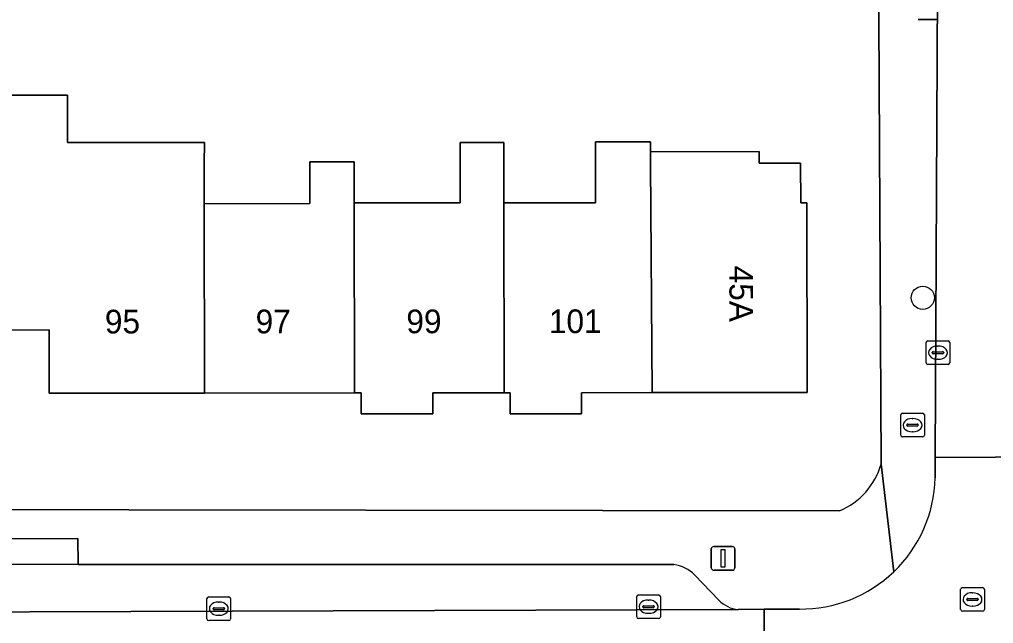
# Model space of a CAD drawing. Extents: x 160732 to 162107, y 387428 to 388479.
# Drawn here: x 161117.3 to 161158.48, y 388134.52 to 388160.04 of the extents above; entities that cross this region are included whole.
import ezdxf

# ---------------------------------------------------------------- set-up
doc = ezdxf.new("R2010")
doc.units = 0
for name, color, linetype in [('IMGEO_Boom', 7, 'Continuous'), ('IMGEO_Brandkraan', 7, 'Continuous'), ('IMGEO_Erf', 7, 'Continuous'), ('IMGEO_Kolk', 7, 'Continuous'), ('IMGEO_Lichtmast', 7, 'Continuous'), ('IMGEO_Pand', 7, 'Continuous'), ('IMGEO_Pand_nummerreeks', 7, 'Continuous'), ('IMGEO_Parkeervlak_open', 7, 'Continuous'), ('IMGEO_Rijbaan_lokaal_open', 7, 'Continuous'), ('IMGEO_Rioolput', 7, 'Continuous'), ('IMGEO_Voetpad_open', 7, 'Continuous')]:
    doc.layers.add(name, color=color, linetype=linetype)

msp = doc.modelspace()

# ---------------------------------------------------------------- linework, layer by layer
at = {"layer": 'IMGEO_Boom'}
msp.add_circle((161155.494, 388148.283), 0.489, dxfattribs=at)
at = {"layer": 'IMGEO_Brandkraan'}
for p, q in [((161154.56, 388142.478), (161154.56, 388143.33)), ((161154.635, 388143.404), (161155.487, 388143.404)), ((161155.561, 388143.33), (161155.561, 388142.478)), ((161154.819, 388142.898), (161154.819, 388142.91)), ((161155.257, 388142.861), (161154.859, 388142.861)), ((161154.862, 388142.947), (161155.26, 388142.947)), ((161155.048, 388143.184), (161155.073, 388143.184)), ((161155.303, 388142.91), (161155.303, 388142.898)), ((161155.071, 388142.624), (161155.046, 388142.624)), ((161155.487, 388142.404), (161154.635, 388142.404))]:
    msp.add_line(p, q, dxfattribs=at)
for points in [[(161154.56, 388142.478), (161154.56, 388143.33)], [(161154.635, 388143.404), (161155.487, 388143.404)], [(161155.561, 388143.33), (161155.561, 388142.478)], [(161155.487, 388142.404), (161154.635, 388142.404)]]:
    msp.add_lwpolyline(points, dxfattribs=at)
for centre, radius, start, end in [((161154.637, 388143.328), 0.0765, 91.552, 178.448), ((161154.637, 388143.328), 0.0765, 91.552, 178.448), ((161155.485, 388143.328), 0.0765, 1.552, 88.448), ((161155.485, 388143.328), 0.0765, 1.552, 88.448), ((161154.859, 388142.907), 0.0403, 85.8775, 175.7526), ((161154.856, 388142.897), 0.0366, 178.938, 274.7102), ((161155.26, 388142.904), 0.043, 264.8664, 352.4533), ((161155.264, 388142.909), 0.0386, 1.7309, 96.639), ((161154.637, 388142.48), 0.0765, 181.552, 268.448), ((161154.637, 388142.48), 0.0765, 181.552, 268.448), ((161155.485, 388142.48), 0.0765, 271.552, 358.448), ((161155.485, 388142.48), 0.0765, 271.552, 358.448)]:
    msp.add_arc(centre, radius, start, end, dxfattribs=at)
for centre, major_axis, ratio, start_param, end_param in [((161155.047, 388142.904), (-0.387, 0.002), 0.722429, 4.712389, 7.853982), ((161155.072, 388142.904), (-0.39, 0.002), 0.717154, 1.570796, 4.712389)]:
    msp.add_ellipse(centre, major_axis=major_axis, ratio=ratio, start_param=start_param, end_param=end_param, dxfattribs=at)
at = {"layer": 'IMGEO_Erf'}
for points in [[(161153.729, 388141.259), (161153.611, 388165.456)], [(161114.927, 388156.851), (161119.327, 388156.851), (161119.327, 388154.851), (161125.122, 388154.851), (161125.111, 388153.956), (161125.113, 388152.259), (161129.583, 388152.262), (161129.581, 388154.025), (161131.454, 388154.026), (161131.455, 388152.296), (161135.932, 388152.3), (161135.93, 388153.961), (161135.929, 388154.839), (161137.783, 388154.84), (161137.784, 388153.963), (161137.785, 388152.297), (161141.655, 388152.3), (161141.653, 388154.868), (161143.981, 388154.869), (161143.984, 388154.444), (161148.568, 388154.468), (161148.571, 388153.968), (161150.329, 388153.969), (161150.331, 388152.298), (161150.593, 388152.299), (161150.6, 388144.279), (161144.045, 388144.274), (161141.066, 388144.272), (161141.066, 388143.374), (161138.043, 388143.374), (161138.043, 388144.269), (161137.79, 388144.269), (161134.772, 388144.267), (161134.772, 388143.374), (161131.749, 388143.374), (161131.749, 388144.264), (161131.46, 388144.264), (161125.122, 388144.259), (161118.554, 388144.254), (161118.552, 388146.923), (161114.927, 388146.921)], [(161091.402, 388139.194), (161098.635, 388139.224), (161111.891, 388139.34), (161151.971, 388139.278)]]:
    msp.add_lwpolyline(points, dxfattribs=at)
msp.add_arc((161150.813, 388142.076), 3.028, 292.4783, 344.3481, dxfattribs=at)
at = {"layer": 'IMGEO_Kolk'}
for p, q in [((161155.633, 388145.537), (161155.633, 388146.389)), ((161155.708, 388146.463), (161156.56, 388146.463)), ((161156.121, 388146.243), (161156.146, 388146.243)), ((161156.634, 388146.389), (161156.634, 388145.537)), ((161155.892, 388145.957), (161155.892, 388145.969)), ((161156.33, 388145.92), (161155.932, 388145.92)), ((161155.935, 388146.006), (161156.333, 388146.006)), ((161156.376, 388145.969), (161156.376, 388145.957)), ((161156.56, 388145.463), (161155.708, 388145.463)), ((161156.144, 388145.683), (161156.119, 388145.683)), ((161125.228, 388134.719), (161125.228, 388135.571)), ((161125.303, 388135.645), (161126.155, 388135.645)), ((161125.716, 388135.425), (161125.741, 388135.425)), ((161126.229, 388135.571), (161126.229, 388134.719)), ((161143.396, 388134.803), (161143.396, 388135.655)), ((161143.471, 388135.729), (161144.323, 388135.729)), ((161143.884, 388135.509), (161143.909, 388135.509)), ((161144.397, 388135.655), (161144.397, 388134.803)), ((161125.487, 388135.139), (161125.487, 388135.151)), ((161125.925, 388135.102), (161125.527, 388135.102)), ((161125.53, 388135.188), (161125.928, 388135.188)), ((161125.971, 388135.151), (161125.971, 388135.139)), ((161143.655, 388135.223), (161143.655, 388135.235)), ((161144.093, 388135.186), (161143.695, 388135.186)), ((161143.698, 388135.272), (161144.096, 388135.272)), ((161144.139, 388135.235), (161144.139, 388135.223)), ((161126.155, 388134.645), (161125.303, 388134.645)), ((161125.739, 388134.865), (161125.714, 388134.865)), ((161144.323, 388134.729), (161143.471, 388134.729)), ((161143.907, 388134.949), (161143.882, 388134.949))]:
    msp.add_line(p, q, dxfattribs=at)
for points in [[(161155.633, 388145.537), (161155.633, 388146.389)], [(161155.708, 388146.463), (161156.56, 388146.463)], [(161156.634, 388146.389), (161156.634, 388145.537)], [(161156.56, 388145.463), (161155.708, 388145.463)], [(161125.228, 388134.719), (161125.228, 388135.571)], [(161125.303, 388135.645), (161126.155, 388135.645)], [(161126.229, 388135.571), (161126.229, 388134.719)], [(161143.396, 388134.803), (161143.396, 388135.655)], [(161143.471, 388135.729), (161144.323, 388135.729)], [(161144.397, 388135.655), (161144.397, 388134.803)], [(161126.155, 388134.645), (161125.303, 388134.645)], [(161144.323, 388134.729), (161143.471, 388134.729)]]:
    msp.add_lwpolyline(points, dxfattribs=at)
for centre, radius, start, end in [((161155.71, 388146.387), 0.0765, 91.552, 178.448), ((161155.71, 388146.387), 0.0765, 91.552, 178.448), ((161156.558, 388146.387), 0.0765, 1.552, 88.448), ((161156.558, 388146.387), 0.0765, 1.552, 88.448), ((161155.932, 388145.966), 0.0403, 85.8775, 175.7526), ((161155.929, 388145.956), 0.0366, 178.938, 274.7102), ((161156.333, 388145.963), 0.043, 264.8664, 352.4533), ((161156.337, 388145.968), 0.0386, 1.7309, 96.639), ((161155.71, 388145.539), 0.0765, 181.552, 268.448), ((161155.71, 388145.539), 0.0765, 181.552, 268.448), ((161156.558, 388145.539), 0.0765, 271.552, 358.448), ((161156.558, 388145.539), 0.0765, 271.552, 358.448), ((161125.305, 388135.569), 0.0765, 91.552, 178.448), ((161125.305, 388135.569), 0.0765, 91.552, 178.448), ((161126.153, 388135.569), 0.0765, 1.552, 88.448), ((161126.153, 388135.569), 0.0765, 1.552, 88.448), ((161143.473, 388135.653), 0.0765, 91.552, 178.448), ((161143.473, 388135.653), 0.0765, 91.552, 178.448), ((161144.321, 388135.653), 0.0765, 1.552, 88.448), ((161144.321, 388135.653), 0.0765, 1.552, 88.448), ((161125.527, 388135.148), 0.0403, 85.8775, 175.7526), ((161125.524, 388135.138), 0.0366, 178.938, 274.7102), ((161125.928, 388135.145), 0.043, 264.8664, 352.4533), ((161125.932, 388135.15), 0.0386, 1.7309, 96.639), ((161143.695, 388135.232), 0.0403, 85.8775, 175.7526), ((161143.692, 388135.222), 0.0366, 178.938, 274.7102), ((161144.096, 388135.229), 0.043, 264.8664, 352.4533), ((161144.1, 388135.234), 0.0386, 1.7309, 96.639), ((161125.305, 388134.721), 0.0765, 181.552, 268.448), ((161125.305, 388134.721), 0.0765, 181.552, 268.448), ((161126.153, 388134.721), 0.0765, 271.552, 358.448), ((161126.153, 388134.721), 0.0765, 271.552, 358.448), ((161143.473, 388134.805), 0.0765, 181.552, 268.448), ((161143.473, 388134.805), 0.0765, 181.552, 268.448), ((161144.321, 388134.805), 0.0765, 271.552, 358.448), ((161144.321, 388134.805), 0.0765, 271.552, 358.448)]:
    msp.add_arc(centre, radius, start, end, dxfattribs=at)
for centre, major_axis, ratio, start_param, end_param in [((161156.12, 388145.963), (-0.387, 0.002), 0.722429, 4.712389, 7.853982), ((161156.145, 388145.963), (-0.39, 0.002), 0.717154, 1.570796, 4.712389), ((161125.715, 388135.145), (-0.387, 0.002), 0.722429, 4.712389, 7.853982), ((161125.74, 388135.145), (-0.39, 0.002), 0.717154, 1.570796, 4.712389), ((161143.883, 388135.229), (-0.387, 0.002), 0.722429, 4.712389, 7.853982), ((161143.908, 388135.229), (-0.39, 0.002), 0.717154, 1.570796, 4.712389)]:
    msp.add_ellipse(centre, major_axis=major_axis, ratio=ratio, start_param=start_param, end_param=end_param, dxfattribs=at)
at = {"layer": 'IMGEO_Lichtmast'}
for p, q in [((161156.082, 388160.042), (161155.292, 388160.042)), ((161155.292, 388160.042), (161156.082, 388160.042)), ((161146.552, 388136.871), (161146.552, 388137.671)), ((161146.552, 388137.671), (161146.552, 388136.871)), ((161146.652, 388137.771), (161147.442, 388137.771)), ((161147.442, 388137.771), (161146.652, 388137.771)), ((161147.542, 388137.671), (161147.542, 388136.871)), ((161147.542, 388136.871), (161147.542, 388137.671)), ((161147.442, 388136.771), (161146.652, 388136.771)), ((161146.652, 388136.771), (161147.442, 388136.771))]:
    msp.add_line(p, q, dxfattribs=at)
msp.add_lwpolyline([(161146.972, 388137.646), (161147.122, 388137.646), (161147.122, 388136.896), (161146.972, 388136.896), (161146.972, 388137.646)], dxfattribs=at)
for centre, start, end in [((161146.652, 388137.671), 90, 180), ((161146.652, 388137.671), 90, 180), ((161147.442, 388137.671), 0, 90), ((161147.442, 388137.671), 360, 90), ((161146.652, 388136.871), 180, 270), ((161146.652, 388136.871), 180, 270), ((161147.442, 388136.871), 270, 0), ((161147.442, 388136.871), 270, 0)]:
    msp.add_arc(centre, 0.1, start, end, dxfattribs=at)
at = {"layer": 'IMGEO_Pand'}
for points in [[(161125.122, 388154.851), (161119.327, 388154.851), (161119.327, 388156.851), (161114.927, 388156.851), (161114.922, 388154.204), (161114.927, 388146.921), (161118.552, 388146.923), (161118.554, 388144.254), (161125.122, 388144.259), (161125.113, 388152.259), (161125.111, 388153.956)], [(161137.785, 388152.297), (161137.784, 388153.963), (161137.783, 388154.84), (161135.929, 388154.839), (161135.93, 388153.961), (161135.932, 388152.3), (161131.455, 388152.296), (161131.46, 388144.264), (161131.749, 388144.264), (161131.749, 388143.374), (161134.772, 388143.374), (161134.772, 388144.267), (161137.79, 388144.269)], [(161143.987, 388153.944), (161143.984, 388154.444), (161143.981, 388154.869), (161141.653, 388154.868), (161141.655, 388152.3), (161137.785, 388152.297), (161137.79, 388144.269), (161138.043, 388144.269), (161138.043, 388143.374), (161141.066, 388143.374), (161141.066, 388144.272), (161144.045, 388144.274)], [(161144.045, 388144.274), (161150.6, 388144.279), (161150.593, 388152.299), (161150.331, 388152.298), (161150.329, 388153.969), (161148.571, 388153.968), (161148.568, 388154.468), (161143.984, 388154.444), (161143.987, 388153.944)], [(161125.122, 388144.259), (161131.46, 388144.264), (161131.455, 388152.296), (161131.454, 388154.026), (161129.581, 388154.025), (161129.583, 388152.262), (161125.113, 388152.259)]]:
    msp.add_lwpolyline(points, close=True, dxfattribs=at)
at = {"layer": 'IMGEO_Parkeervlak_open'}
for points in [[(161119.782, 388137.014), (161110.754, 388137.021)], [(161144.962, 388137.01), (161119.782, 388137.014)], [(161146.875, 388135.509), (161145.848, 388136.568)], [(161087.767, 388134.917), (161147.688, 388135.104)]]:
    msp.add_lwpolyline(points, dxfattribs=at)
for centre, radius, start, end in [((161144.762, 388135.501), 1.523, 44.5117, 82.4617), ((161147.83, 388136.407), 1.311, 223.2528, 263.7864)]:
    msp.add_arc(centre, radius, start, end, dxfattribs=at)
at = {"layer": 'IMGEO_Rijbaan_lokaal_open'}
for points in [[(161160.946, 388193.594), (161160.967, 388195.059), (161160.943, 388223.645), (161155.942, 388223.612), (161156.12, 388166.254), (161156.114, 388161.291), (161156.023, 388141.534), (161161.118, 388141.556), (161160.945, 388175.907)], [(161161.118, 388141.556), (161156.023, 388141.534), (161156.019, 388140.67)], [(161147.688, 388135.104), (161087.767, 388134.917)], [(161148.781, 388135.121), (161147.688, 388135.104)], [(161150.274, 388135.131), (161148.781, 388135.121), (161148.814, 388130.087), (161149.577, 388130.075)], [(161148.814, 388130.087), (161148.781, 388135.121)]]:
    msp.add_lwpolyline(points, dxfattribs=at)
for centre, radius, start, end in [((161150.337, 388140.812), 5.684, 313.7184, 358.5659), ((161150.343, 388140.806), 5.676, 269.3076, 313.7148)]:
    msp.add_arc(centre, radius, start, end, dxfattribs=at)
at = {"layer": 'IMGEO_Rioolput'}
for p, q in [((161157.094, 388135.112), (161157.094, 388135.964)), ((161157.169, 388136.038), (161158.021, 388136.038)), ((161157.582, 388135.818), (161157.607, 388135.818)), ((161158.095, 388135.964), (161158.095, 388135.112)), ((161157.353, 388135.532), (161157.353, 388135.544)), ((161157.791, 388135.495), (161157.393, 388135.495)), ((161157.396, 388135.581), (161157.794, 388135.581)), ((161157.837, 388135.544), (161157.837, 388135.532)), ((161158.021, 388135.038), (161157.169, 388135.038)), ((161157.605, 388135.258), (161157.58, 388135.258))]:
    msp.add_line(p, q, dxfattribs=at)
for points in [[(161157.094, 388135.112), (161157.094, 388135.964)], [(161157.169, 388136.038), (161158.021, 388136.038)], [(161158.095, 388135.964), (161158.095, 388135.112)], [(161158.021, 388135.038), (161157.169, 388135.038)]]:
    msp.add_lwpolyline(points, dxfattribs=at)
for centre, radius, start, end in [((161157.171, 388135.962), 0.0765, 91.552, 178.448), ((161157.171, 388135.962), 0.0765, 91.552, 178.448), ((161158.019, 388135.962), 0.0765, 1.552, 88.448), ((161158.019, 388135.962), 0.0765, 1.552, 88.448), ((161157.393, 388135.541), 0.0403, 85.8775, 175.7526), ((161157.39, 388135.531), 0.0366, 178.938, 274.7102), ((161157.794, 388135.538), 0.043, 264.8664, 352.4533), ((161157.798, 388135.543), 0.0386, 1.7309, 96.639), ((161157.171, 388135.114), 0.0765, 181.552, 268.448), ((161157.171, 388135.114), 0.0765, 181.552, 268.448), ((161158.019, 388135.114), 0.0765, 271.552, 358.448), ((161158.019, 388135.114), 0.0765, 271.552, 358.448)]:
    msp.add_arc(centre, radius, start, end, dxfattribs=at)
for centre, major_axis, ratio, start_param, end_param in [((161157.581, 388135.538), (-0.387, 0.002), 0.722429, 4.712389, 7.853982), ((161157.606, 388135.538), (-0.39, 0.002), 0.717154, 1.570796, 4.712389)]:
    msp.add_ellipse(centre, major_axis=major_axis, ratio=ratio, start_param=start_param, end_param=end_param, dxfattribs=at)
at = {"layer": 'IMGEO_Voetpad_open'}
for points in [[(161156.114, 388161.291), (161155.002, 388161.286), (161154.974, 388166.212), (161156.12, 388166.254), (161155.942, 388223.612), (161153.48, 388224.813), (161153.568, 388207.782), (161153.588, 388170.261), (161153.606, 388166.499), (161153.611, 388165.456), (161153.729, 388141.259), (161154.265, 388136.704)], [(161156.019, 388140.67), (161156.023, 388141.534), (161156.114, 388161.291)], [(161154.265, 388136.704), (161153.729, 388141.259)], [(161151.971, 388139.278), (161111.891, 388139.34), (161098.635, 388139.224), (161091.402, 388139.194)], [(161090.746, 388136.938), (161110.754, 388137.021), (161110.72, 388138.081), (161119.766, 388138.111), (161119.782, 388137.014), (161144.962, 388137.01)], [(161145.848, 388136.568), (161146.875, 388135.509)], [(161147.688, 388135.104), (161148.781, 388135.121), (161150.274, 388135.131)]]:
    msp.add_lwpolyline(points, dxfattribs=at)
msp.add_lwpolyline([(161110.754, 388137.021), (161119.782, 388137.014), (161119.766, 388138.111), (161110.72, 388138.081)], close=True, dxfattribs=at)
for centre, radius, start, end in [((161150.813, 388142.076), 3.028, 292.4783, 344.3481), ((161150.337, 388140.812), 5.684, 313.7184, 358.5659), ((161144.762, 388135.501), 1.523, 44.5117, 82.4617), ((161150.343, 388140.806), 5.676, 269.3076, 313.7148), ((161147.83, 388136.407), 1.311, 223.2528, 263.7864)]:
    msp.add_arc(centre, radius, start, end, dxfattribs=at)

# ---------------------------------------------------------------- texts
at = {"layer": 'IMGEO_Pand_nummerreeks'}
for s, rotation, p in [('45A', 270.05, (161147.316, 388149.642)), ('95', 0.0447, (161120.912, 388146.776)), ('97', 0.0447, (161127.285, 388146.781)), ('99', 0.0458, (161133.658, 388146.785)), ('101', 0.0458, (161139.683, 388146.791))]:
    msp.add_text(s, height=1, rotation=rotation, dxfattribs=at).set_placement(p)

doc.saveas('drawing.dxf')
